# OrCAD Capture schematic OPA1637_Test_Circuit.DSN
size A; title: OPA1637 High-Fidelity, Low-Noise, Fully-Differential,; rev: 1.1; note: Datasheet: SBOSA00B   EVM: SBOU235A
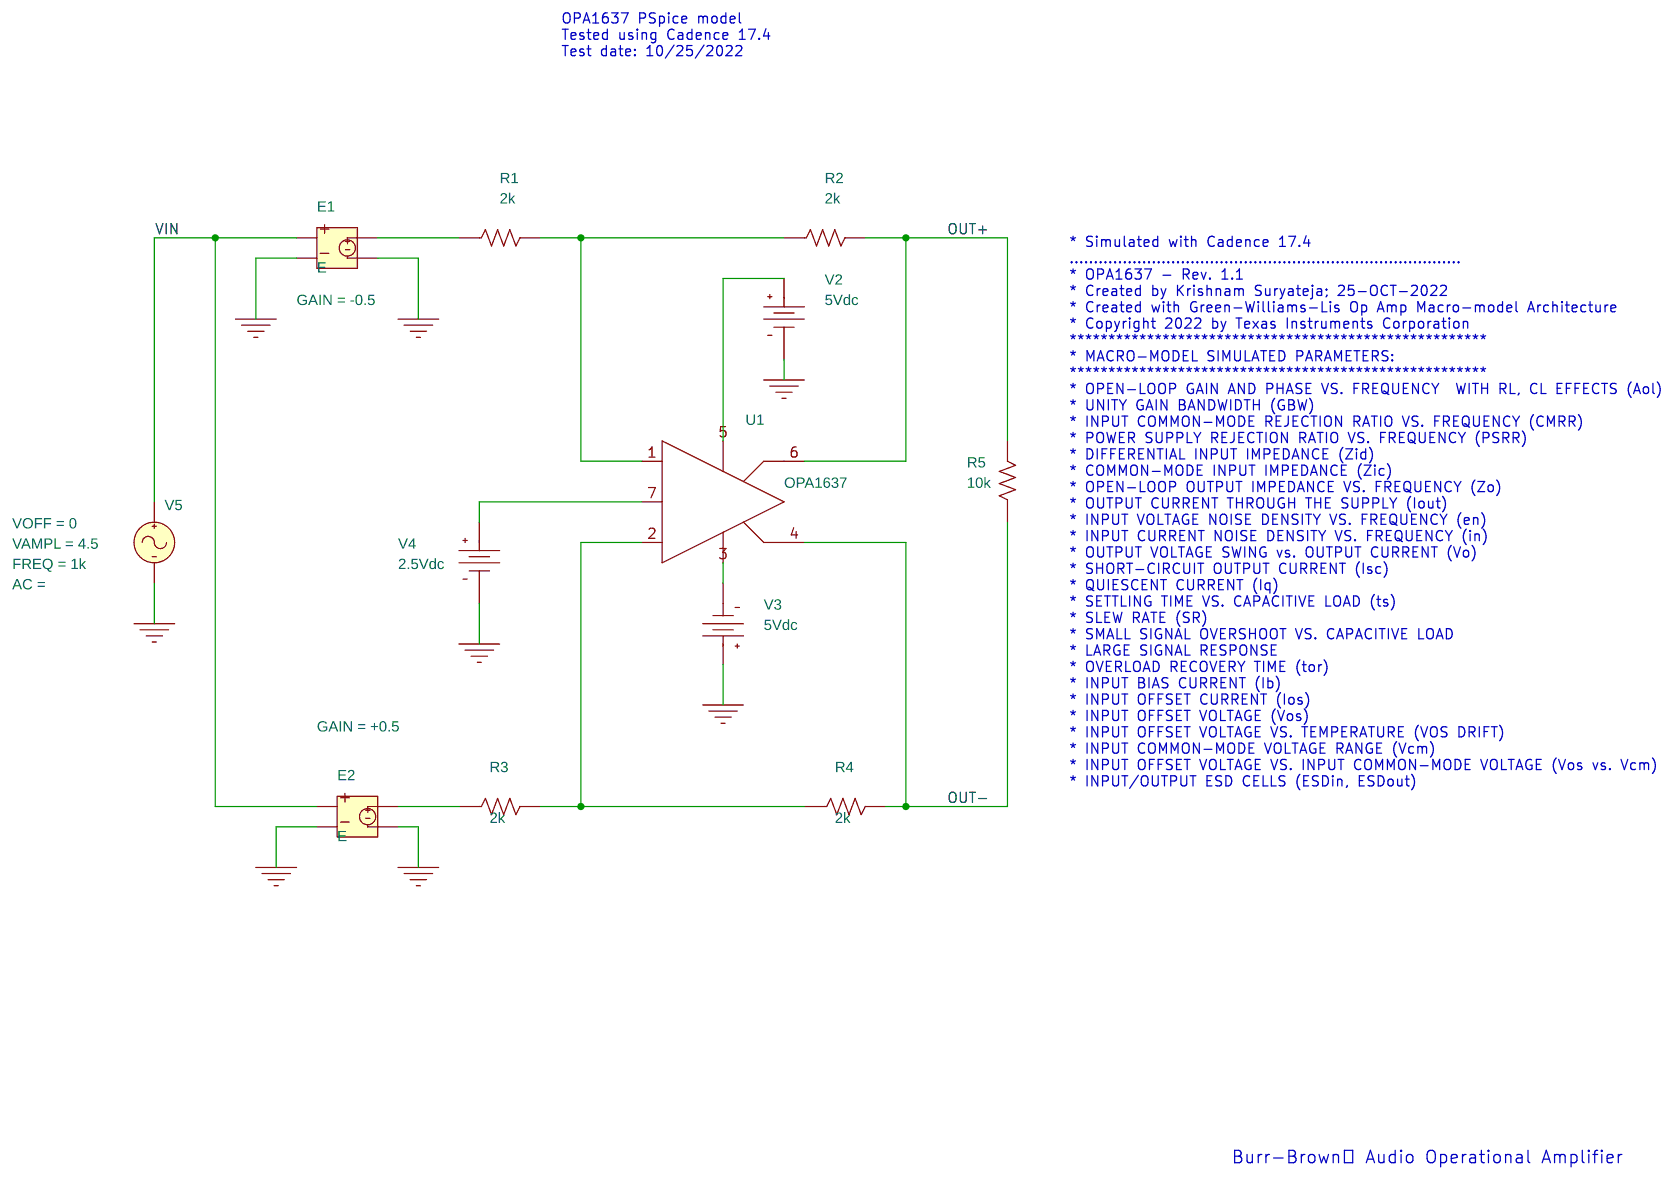
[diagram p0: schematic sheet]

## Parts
E1  E
E2  E
R1  2k  [AX/RC05]
R2  2k  [AX/RC05]
R3  2k  [AX/RC05]
R4  2k  [AX/RC05]
R5  10k  [AX/RC05]
U1  OPA1637
V2  VDC
V3  VDC
V4  VDC
V5  VSIN

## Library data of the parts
E1 = E: GAIN: -0.5
E2 = E: GAIN: +0.5
R1-R5 = R
U1 = OPA1637
V2 V3 = VDC: DC: 5Vdc
V4 = VDC: DC: 2.5Vdc
V5 = VSIN: FREQ: 1k; VAMPL: 4.5; VOFF: 0

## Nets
VIN: E1.1 E2.1 V5.1(+)
0: E1.2 E1.4 E2.2 E2.4 V2.1(-) V3.0(+) V4.1(-) V5.2(-)
OUT+: R2.2 R5.2 U1.6(OUT+)
OUT-: R4.2 R5.1 U1.4(OUT-)
N00371: E1.3 R1.1
N00375: R1.2 R2.1 U1.1(-)
N00412: R3.2 R4.1 U1.2(+)
N00446: E2.3 R3.1
N00549: U1.5(V+) V2.0(+)
N00651: U1.7(VOCM) V4.0(+)
N37223: U1.3(V-) V3.1(-)

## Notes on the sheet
- OPA1637 PSpice model
  Tested using Cadence 17.4
  Test date: 10/25/2022
- * Simulated with Cadence 17.4
  .................................................................................
  * OPA1637 - Rev. 1.1
  * Created by Krishnam Suryateja; 25-OCT-2022
  * Created with Green-Williams-Lis Op Amp Macro-model Architecture
  * Copyright 2022 by Texas Instruments Corporation
  ******************************************************
  * MACRO-MODEL SIMULATED PARAMETERS:
  ******************************************************
  * OPEN-LOOP GAIN AND PHASE VS. FREQUENCY  WITH RL, CL EFFECTS (Aol)
  * UNITY GAIN BANDWIDTH (GBW)
  * INPUT COMMON-MODE REJECTION RATIO VS. FREQUENCY (CMRR)
  * POWER SUPPLY REJECTION RATIO VS. FREQUENCY (PSRR)
  * DIFFERENTIAL INPUT IMPEDANCE (Zid)
  * COMMON-MODE INPUT IMPEDANCE (Zic)
  * OPEN-LOOP OUTPUT IMPEDANCE VS. FREQUENCY (Zo)
  * OUTPUT CURRENT THROUGH THE SUPPLY (Iout)
  * INPUT VOLTAGE NOISE DENSITY VS. FREQUENCY (en)
  * INPUT CURRENT NOISE DENSITY VS. FREQUENCY (in)
  * OUTPUT VOLTAGE SWING vs. OUTPUT CURRENT (Vo)
  * SHORT-CIRCUIT OUTPUT CURRENT (Isc)
  * QUIESCENT CURRENT (Iq)
  * SETTLING TIME VS. CAPACITIVE LOAD (ts)
  * SLEW RATE (SR)
  * SMALL SIGNAL OVERSHOOT VS. CAPACITIVE LOAD
  * LARGE SIGNAL RESPONSE
  * OVERLOAD RECOVERY TIME (tor)
  * INPUT BIAS CURRENT (Ib)
  * INPUT OFFSET CURRENT (Ios)
  * INPUT OFFSET VOLTAGE (Vos)
  * INPUT OFFSET VOLTAGE VS. TEMPERATURE (VOS DRIFT)
  * INPUT COMMON-MODE VOLTAGE RANGE (Vcm)
  * INPUT OFFSET VOLTAGE VS. INPUT COMMON-MODE VOLTAGE (Vos vs. Vcm)
  * INPUT/OUTPUT ESD CELLS (ESDin, ESDout)
- Burr-Brown™ Audio Operational Amplifier
